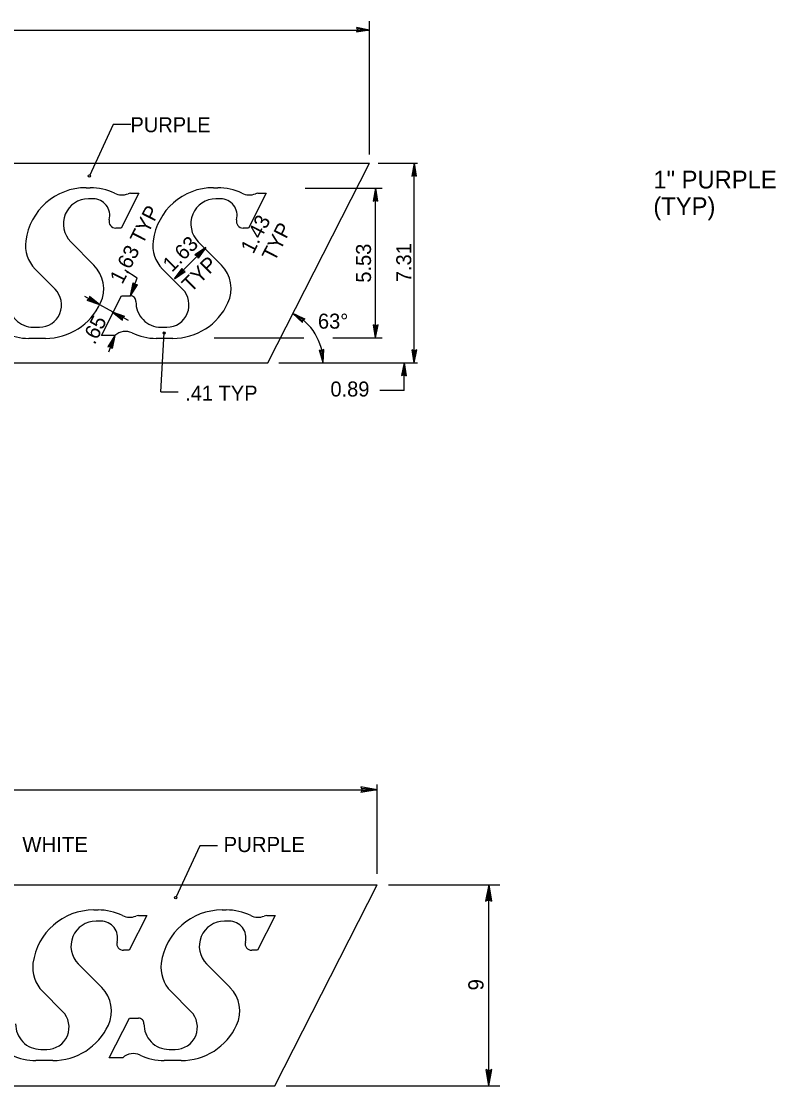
# Model space of a CAD drawing. Extents: x 10268197 to 10269179, y 2141503 to 2142677.
# Drawn here: x 10268622.88 to 10268652.8, y 2142123.35 to 2142165.55 of the extents above; entities that cross this region are included whole.
import ezdxf

# ---------------------------------------------------------------- set-up
doc = ezdxf.new("R2010")
doc.units = 0
for name, color, linetype in [('1', 7, 'Continuous'), ('21', 7, 'Continuous'), ('Default', 7, 'Continuous')]:
    doc.layers.add(name, color=color, linetype=linetype)

msp = doc.modelspace()

# ---------------------------------------------------------------- linework, layer by layer
at = {"layer": '1'}
for p, q in [((10268636.689, 2142160.267), (10268636.689, 2142165.546)), ((10268617.622, 2142165.194), (10268636.689, 2142165.194)), ((10268636.216, 2142165.203), (10268636.175, 2142165.112)), ((10268636.689, 2142165.194), (10268636.175, 2142165.112)), ((10268636.689, 2142165.194), (10268636.178, 2142165.293)), ((10268636.178, 2142165.293), (10268636.216, 2142165.203)), ((10268636.689, 2142165.194), (10268636.197, 2142165.16)), ((10268636.689, 2142165.194), (10268636.198, 2142165.246)), ((10268626.531, 2142161.456), (10268625.584, 2142159.412)), ((10268627.229, 2142161.456), (10268626.531, 2142161.456)), ((10268637.04, 2142159.916), (10268638.595, 2142159.916)), ((10268638.462, 2142159.916), (10268638.363, 2142159.405)), ((10268638.462, 2142159.916), (10268638.411, 2142159.424)), ((10268638.462, 2142152.007), (10268638.462, 2142159.916)), ((10268638.462, 2142159.916), (10268638.543, 2142159.402)), ((10268638.462, 2142159.916), (10268638.496, 2142159.424)), ((10268638.363, 2142159.405), (10268638.454, 2142159.442)), ((10268638.454, 2142159.442), (10268638.543, 2142159.402)), ((10268634.139, 2142158.927), (10268637.197, 2142158.927)), ((10268636.931, 2142158.927), (10268636.832, 2142158.416)), ((10268636.931, 2142158.927), (10268636.879, 2142158.436)), ((10268636.931, 2142152.996), (10268636.931, 2142158.927)), ((10268636.931, 2142158.927), (10268637.012, 2142158.413)), ((10268636.931, 2142158.927), (10268636.965, 2142158.435)), ((10268636.832, 2142158.416), (10268636.922, 2142158.454)), ((10268636.922, 2142158.454), (10268637.012, 2142158.413)), ((10268628.955, 2142155.33), (10268630.198, 2142156.573)), ((10268630.198, 2142156.573), (10268629.767, 2142156.282)), ((10268629.767, 2142156.282), (10268629.858, 2142156.244)), ((10268630.198, 2142156.573), (10268629.814, 2142156.262)), ((10268629.858, 2142156.244), (10268629.892, 2142156.152)), ((10268630.198, 2142156.573), (10268629.874, 2142156.201)), ((10268630.198, 2142156.573), (10268629.892, 2142156.152)), ((10268627.483, 2142155.362), (10268626.994, 2142155.673)), ((10268628.955, 2142155.33), (10268629.261, 2142155.751)), ((10268628.955, 2142155.33), (10268629.279, 2142155.702)), ((10268628.955, 2142155.33), (10268629.339, 2142155.641)), ((10268628.955, 2142155.33), (10268629.387, 2142155.622)), ((10268629.295, 2142155.659), (10268629.261, 2142155.751)), ((10268629.387, 2142155.622), (10268629.295, 2142155.659)), ((10268627.209, 2142154.662), (10268627.483, 2142155.362)), ((10268627.209, 2142154.662), (10268627.32, 2142155.171)), ((10268627.209, 2142154.662), (10268627.356, 2142155.133)), ((10268627.209, 2142154.662), (10268627.487, 2142155.102)), ((10268627.209, 2142154.662), (10268627.435, 2142155.101)), ((10268627.388, 2142155.1), (10268627.32, 2142155.171)), ((10268627.487, 2142155.102), (10268627.388, 2142155.1)), ((10268625.992, 2142154.306), (10268625.398, 2142154.63)), ((10268626.378, 2142154.096), (10268625.992, 2142154.306)), ((10268627.13, 2142153.686), (10268626.378, 2142154.096)), ((10268633.656, 2142153.965), (10268634.132, 2142153.753)), ((10268633.656, 2142153.965), (10268634.031, 2142153.603)), ((10268633.656, 2142153.965), (10268634.04, 2142153.654)), ((10268633.656, 2142153.965), (10268634.088, 2142153.726)), ((10268634.049, 2142153.7), (10268634.132, 2142153.753)), ((10268634.031, 2142153.603), (10268634.049, 2142153.7)), ((10268636.931, 2142152.996), (10268636.849, 2142153.51)), ((10268636.938, 2142153.469), (10268636.849, 2142153.51)), ((10268636.931, 2142152.996), (10268636.896, 2142153.488)), ((10268636.931, 2142152.996), (10268637.029, 2142153.507)), ((10268636.931, 2142152.996), (10268636.982, 2142153.487)), ((10268637.029, 2142153.507), (10268636.938, 2142153.469)), ((10268626.592, 2142153.085), (10268626.313, 2142152.645)), ((10268626.592, 2142153.085), (10268626.335, 2142152.43)), ((10268626.592, 2142153.085), (10268626.364, 2142152.646)), ((10268626.592, 2142153.085), (10268626.444, 2142152.614)), ((10268626.592, 2142153.085), (10268626.48, 2142152.576)), ((10268628.414, 2142150.852), (10268628.549, 2142153.189)), ((10268630.526, 2142152.996), (10268634.088, 2142152.996)), ((10268635.236, 2142152.996), (10268637.197, 2142152.996)), ((10268626.313, 2142152.645), (10268626.411, 2142152.647)), ((10268626.411, 2142152.647), (10268626.48, 2142152.576)), ((10268634.856, 2142152.007), (10268634.704, 2142152.505)), ((10268634.798, 2142152.477), (10268634.704, 2142152.505)), ((10268634.856, 2142152.007), (10268634.753, 2142152.49)), ((10268634.884, 2142152.527), (10268634.798, 2142152.477)), ((10268634.856, 2142152.007), (10268634.839, 2142152.501)), ((10268634.856, 2142152.007), (10268634.884, 2142152.527)), ((10268638.462, 2142152.007), (10268638.38, 2142152.521)), ((10268638.47, 2142152.48), (10268638.38, 2142152.521)), ((10268638.462, 2142152.007), (10268638.427, 2142152.499)), ((10268638.462, 2142152.007), (10268638.561, 2142152.518)), ((10268638.462, 2142152.007), (10268638.513, 2142152.499)), ((10268638.561, 2142152.518), (10268638.47, 2142152.48)), ((10268633.098, 2142152.007), (10268638.595, 2142152.007)), ((10268638.061, 2142152.007), (10268637.962, 2142151.497)), ((10268638.061, 2142152.007), (10268638.01, 2142151.516)), ((10268638.061, 2142150.909), (10268638.061, 2142152.007)), ((10268638.061, 2142152.007), (10268638.143, 2142151.494)), ((10268638.061, 2142152.007), (10268638.096, 2142151.515)), ((10268637.962, 2142151.497), (10268638.053, 2142151.534)), ((10268638.053, 2142151.534), (10268638.143, 2142151.494)), ((10268628.414, 2142150.852), (10268629.097, 2142150.852)), ((10268638.061, 2142150.909), (10268637.106, 2142150.909)), ((10268636.996, 2142131.752), (10268636.996, 2142135.291)), ((10268617.796, 2142135.07), (10268636.996, 2142135.07)), ((10268629.961, 2142132.861), (10268629.008, 2142130.802)), ((10268630.664, 2142132.861), (10268629.961, 2142132.861)), ((10268637.439, 2142131.31), (10268641.863, 2142131.31)), ((10268641.421, 2142123.346), (10268641.421, 2142131.31)), ((10268633.381, 2142123.346), (10268641.863, 2142123.346))]:
    msp.add_line(p, q, dxfattribs=at)
for centre, radius in [((10268625.584, 2142159.412), 0.0439), ((10268628.549, 2142153.189), 0.0439), ((10268629.008, 2142130.802), 0.0442)]:
    msp.add_circle(centre, radius, dxfattribs=at)
msp.add_arc((10268632.659, 2142152.008), 2.197, 0, 63.0012, dxfattribs=at)
at = {"layer": '21'}
for p, q in [((10268625.59, 2142154.639), (10268625.58, 2142154.54)), ((10268625.992, 2142154.306), (10268625.585, 2142154.587)), ((10268625.992, 2142154.306), (10268625.59, 2142154.639)), ((10268625.58, 2142154.54), (10268625.501, 2142154.481)), ((10268625.992, 2142154.306), (10268625.501, 2142154.481)), ((10268625.992, 2142154.306), (10268625.543, 2142154.512)), ((10268626.49, 2142154.032), (10268626.981, 2142153.858)), ((10268626.49, 2142154.032), (10268626.892, 2142153.7)), ((10268626.49, 2142154.032), (10268626.897, 2142153.752)), ((10268626.49, 2142154.032), (10268626.939, 2142153.826)), ((10268626.892, 2142153.7), (10268626.902, 2142153.798)), ((10268626.902, 2142153.798), (10268626.981, 2142153.858))]:
    msp.add_line(p, q, dxfattribs=at)
at = {"layer": 'Default'}
for p, q in [((10268611.626, 2142159.916), (10268636.689, 2142159.916)), ((10268632.66, 2142152.007), (10268636.689, 2142159.916)), ((10268625.453, 2142158.949), (10268625.619, 2142158.949)), ((10268630.505, 2142158.949), (10268630.672, 2142158.949)), ((10268625.731, 2142158.507), (10268625.542, 2142158.507)), ((10268627.543, 2142158.728), (10268626.845, 2142157.347)), ((10268627.213, 2142158.728), (10268627.543, 2142158.728)), ((10268630.783, 2142158.507), (10268630.594, 2142158.507)), ((10268632.595, 2142158.728), (10268631.897, 2142157.347)), ((10268632.266, 2142158.728), (10268632.595, 2142158.728)), ((10268626.845, 2142157.347), (10268626.625, 2142157.347)), ((10268631.897, 2142157.347), (10268631.677, 2142157.347)), ((10268624.843, 2142156.806), (10268625.764, 2142155.879)), ((10268629.896, 2142156.806), (10268630.817, 2142155.879)), ((10268624.223, 2142154.928), (10268623.432, 2142155.724)), ((10268629.275, 2142154.928), (10268628.484, 2142155.724)), ((10268626.058, 2142153.085), (10268626.856, 2142154.662)), ((10268626.856, 2142154.662), (10268627.209, 2142154.662)), ((10268623.364, 2142153.417), (10268623.602, 2142153.417)), ((10268628.417, 2142153.417), (10268628.654, 2142153.417)), ((10268623.837, 2142152.974), (10268623.177, 2142152.974)), ((10268626.592, 2142153.085), (10268626.058, 2142153.085)), ((10268628.89, 2142152.974), (10268628.229, 2142152.974)), ((10268610.892, 2142152.007), (10268632.66, 2142152.007)), ((10268636.996, 2142135.07), (10268636.353, 2142135.195)), ((10268636.353, 2142135.195), (10268636.401, 2142135.08)), ((10268636.401, 2142135.08), (10268636.349, 2142134.967)), ((10268636.996, 2142135.07), (10268636.349, 2142134.967)), ((10268636.996, 2142135.07), (10268636.377, 2142135.027)), ((10268636.996, 2142135.07), (10268636.378, 2142135.135)), ((10268611.758, 2142131.31), (10268636.996, 2142131.31)), ((10268632.938, 2142123.346), (10268636.996, 2142131.31)), ((10268641.421, 2142131.31), (10268641.296, 2142130.667)), ((10268641.421, 2142131.31), (10268641.356, 2142130.692)), ((10268641.421, 2142131.31), (10268641.523, 2142130.663)), ((10268641.421, 2142131.31), (10268641.464, 2142130.69)), ((10268641.296, 2142130.667), (10268641.41, 2142130.714)), ((10268641.41, 2142130.714), (10268641.523, 2142130.663)), ((10268625.757, 2142130.314), (10268625.925, 2142130.314)), ((10268627.862, 2142130.092), (10268627.158, 2142128.713)), ((10268627.53, 2142130.092), (10268627.862, 2142130.092)), ((10268630.845, 2142130.314), (10268631.013, 2142130.314)), ((10268632.95, 2142130.092), (10268632.247, 2142128.713)), ((10268632.618, 2142130.092), (10268632.95, 2142130.092)), ((10268626.037, 2142129.871), (10268625.848, 2142129.871)), ((10268631.125, 2142129.871), (10268630.935, 2142129.871)), ((10268627.158, 2142128.713), (10268626.937, 2142128.713)), ((10268632.247, 2142128.713), (10268632.025, 2142128.713)), ((10268625.143, 2142128.172), (10268626.071, 2142127.245)), ((10268630.232, 2142128.172), (10268631.159, 2142127.245)), ((10268624.518, 2142126.294), (10268623.722, 2142127.09)), ((10268629.606, 2142126.294), (10268628.811, 2142127.09)), ((10268626.367, 2142124.452), (10268627.17, 2142126.029)), ((10268627.17, 2142126.029), (10268627.526, 2142126.029)), ((10268623.654, 2142124.783), (10268623.893, 2142124.783)), ((10268628.742, 2142124.783), (10268628.98, 2142124.783)), ((10268624.131, 2142124.341), (10268623.465, 2142124.341)), ((10268626.904, 2142124.452), (10268626.367, 2142124.452)), ((10268629.218, 2142124.341), (10268628.553, 2142124.341)), ((10268641.421, 2142123.346), (10268641.318, 2142123.993)), ((10268641.43, 2142123.941), (10268641.318, 2142123.993)), ((10268641.421, 2142123.346), (10268641.377, 2142123.965)), ((10268641.421, 2142123.346), (10268641.545, 2142123.989)), ((10268641.421, 2142123.346), (10268641.485, 2142123.964)), ((10268641.545, 2142123.989), (10268641.43, 2142123.941)), ((10268611.171, 2142123.346), (10268632.938, 2142123.346))]:
    msp.add_line(p, q, dxfattribs=at)
for centre, radius, start, end in [((10268625.757, 2142127.88), 2.433, 90, 172.3089), ((10268625.925, 2142128.101), 2.212, 64.0896, 90), ((10268627.181, 2142130.688), 0.664, 244.0896, 292.0347), ((10268627.53, 2142129.827), 0.265, 90, 112.0347), ((10268630.845, 2142127.88), 2.433, 90, 172.3089), ((10268631.013, 2142128.101), 2.212, 64.0896, 90), ((10268632.269, 2142130.688), 0.664, 244.0896, 292.0347), ((10268632.618, 2142129.827), 0.265, 90, 112.0347), ((10268625.847, 2142128.876), 0.995, 90, 225), ((10268626.037, 2142129.207), 0.664, 345.6915, 90), ((10268630.935, 2142128.876), 0.995, 90, 225), ((10268631.125, 2142129.207), 0.664, 345.6915, 90), ((10268626.937, 2142128.978), 0.265, 165.6915, 270), ((10268632.025, 2142128.978), 0.265, 165.6915, 270), ((10268624.661, 2142128.028), 1.327, 172.3089, 225), ((10268629.749, 2142128.028), 1.327, 172.3089, 225), ((10268625.132, 2142126.306), 1.327, 334.95, 45), ((10268630.22, 2142126.306), 1.327, 334.95, 45), ((10268623.892, 2142125.668), 0.885, 270, 45), ((10268628.98, 2142125.668), 0.885, 270, 45), ((10268627.526, 2142125.807), 0.221, 358.6664, 90), ((10268623.654, 2142125.779), 0.995, 178.6665, 270), ((10268624.13, 2142126.774), 2.433, 270, 334.95), ((10268628.742, 2142125.779), 0.995, 178.6665, 270), ((10268629.218, 2142126.774), 2.433, 270, 334.95), ((10268627.328, 2142124), 0.619, 64.3795, 133.1892), ((10268623.465, 2142126.553), 2.212, 244.3795, 270), ((10268628.553, 2142126.553), 2.212, 244.3795, 270)]:
    msp.add_arc(centre, radius, start, end, dxfattribs=at)
for centre, major_axis, start_param, end_param in [((10268625.452, 2142156.515), (0, 2.434), 0, 1.436562), ((10268625.619, 2142156.736), (0, 2.213), 5.830963, 6.283185), ((10268630.505, 2142156.515), (0, 2.434), 0, 1.436562), ((10268630.672, 2142156.736), (0, 2.213), 5.830963, 6.283185), ((10268625.542, 2142157.511), (0, -0.996), 3.141593, 5.497787), ((10268625.731, 2142157.843), (0, -0.664), 1.321066, 3.141593), ((10268626.867, 2142159.324), (0, 0.664), 2.68937, 3.526171), ((10268627.213, 2142158.463), (0, 0.266), 0, 0.384579), ((10268630.595, 2142157.511), (0, -0.996), 3.141593, 5.497787), ((10268630.783, 2142157.843), (0, -0.664), 1.321066, 3.141593), ((10268631.919, 2142159.324), (0, 0.664), 2.68937, 3.526171), ((10268632.266, 2142158.463), (0, 0.266), 0, 0.384579), ((10268626.625, 2142157.613), (0, -0.266), 4.462658, 6.283185), ((10268631.677, 2142157.613), (0, -0.266), 4.462658, 6.283185), ((10268624.364, 2142156.663), (0, 1.328), 1.436562, 2.356194), ((10268629.416, 2142156.663), (0, 1.328), 1.436562, 2.356194), ((10268624.832, 2142154.94), (0, -1.328), 1.133591, 2.356194), ((10268629.885, 2142154.94), (0, -1.328), 1.133591, 2.356194), ((10268623.601, 2142154.302), (0, -0.885), 0, 2.356194), ((10268627.209, 2142154.441), (0, 0.221), 4.689114, 6.283185), ((10268628.654, 2142154.302), (0, -0.885), 0, 2.356194), ((10268623.364, 2142154.413), (0, 0.996), 1.547521, 3.141593), ((10268623.837, 2142155.408), (0, -2.434), 0, 1.133591), ((10268628.417, 2142154.413), (0, 0.996), 1.547521, 3.141593), ((10268628.89, 2142155.408), (0, -2.434), 0, 1.133591), ((10268627.013, 2142152.633), (0, -0.62), 2.69443, 3.895387), ((10268623.176, 2142155.187), (0, -2.213), 5.836023, 6.283185), ((10268628.229, 2142155.187), (0, -2.213), 5.836023, 6.283185)]:
    msp.add_ellipse(centre, major_axis=major_axis, ratio=0.992614, start_param=start_param, end_param=end_param, dxfattribs=at)

# ---------------------------------------------------------------- texts
at = {"layer": '1'}
for s, height, p in [('PURPLE', 0.5942, (10268627.211, 2142161.148)), ('1" PURPLE', 0.7047, (10268647.947, 2142158.919)), ('(TYP)', 0.7047, (10268647.947, 2142157.862)), ('63°', 0.5942, (10268634.646, 2142153.36)), ('0.89', 0.5942, (10268635.141, 2142150.67)), ('.41 TYP', 0.5942, (10268629.381, 2142150.507)), ('WHITE', 0.6037, (10268622.923, 2142132.609)), ('PURPLE', 0.6037, (10268630.903, 2142132.609))]:
    msp.add_text(s, height=height, dxfattribs=at).set_placement(p)
for s, height, rotation, p in [('1.63 TYP', 0.5942, 62.9994, (10268626.89, 2142155.09)), ('1.43', 0.5942, 63, (10268632.08, 2142156.29)), ('TYP', 0.5942, 63, (10268632.925, 2142155.985)), ('1.63', 0.5942, 45, (10268628.851, 2142155.57)), ('5.53', 0.5942, 90, (10268636.75, 2142155.182)), ('7.31', 0.5942, 90, (10268638.346, 2142155.202)), ('TYP', 0.5942, 45, (10268629.613, 2142154.768)), ('.65', 0.5942, 63, (10268625.788, 2142152.695)), ('9', 0.604, 90, (10268641.213, 2142127.123))]:
    msp.add_text(s, height=height, rotation=rotation, dxfattribs=at).set_placement(p)

doc.saveas('drawing.dxf')
